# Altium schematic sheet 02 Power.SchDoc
size 386 x 246 mm
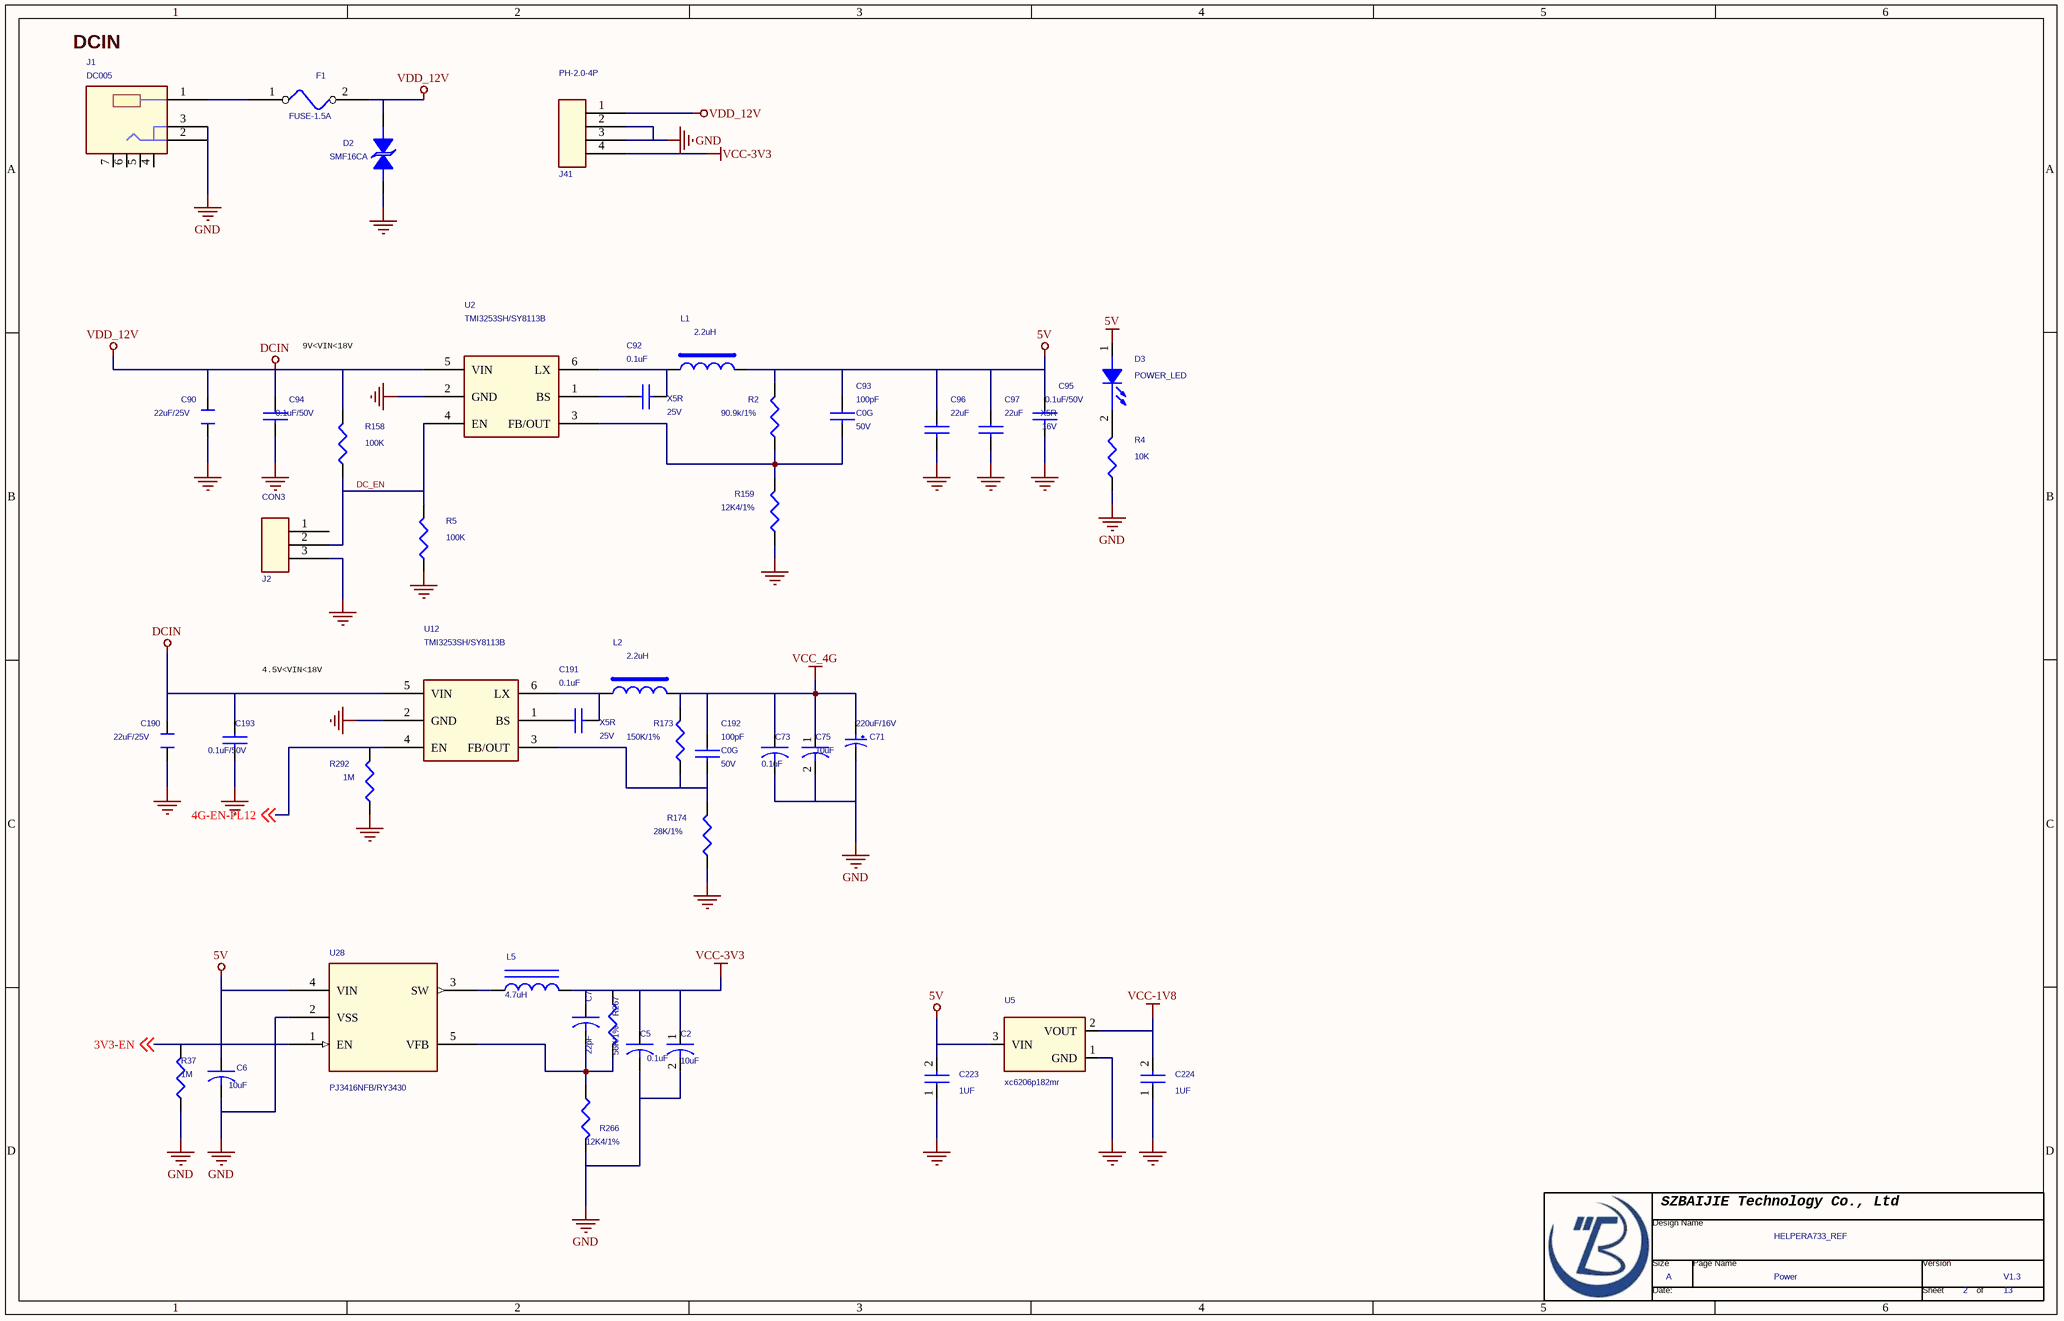
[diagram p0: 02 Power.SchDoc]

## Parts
*  Page Count: 13  Page Number: 2  Page Size: A  Title: HELPERA733_REF  RevCode: V1.3  Doc: Power  (hidden comment: TitleBlock0-BJ)  (graphical)
C2  10uF  [C0603]
C5  0.1uF  [C0402]
C6  10uF  [C0603]
C7  22pF  [C0402]
C71  220uF/16V  [RB.1/.3]
C73  0.1uF  [C0402]
C75  10uF  [C0603]
C90  22uF/25V  [C0805]
C92  0.1uF  Voltage: 25V  Dielectric: X5R  [C0402]
C93  100pF  Voltage: 50V  Dielectric: C0G  [C0402]
C94  0.1uF/50V  [C0402]
C95  0.1uF/50V  Voltage: 16V  Dielectric: X5R  [C0402]
C96  22uF  [C0805]
C97  22uF  [C0805]
C190  22uF/25V  [C0805]
C191  0.1uF  Voltage: 25V  Dielectric: X5R  [C0402]
C192  100pF  Voltage: 50V  Dielectric: C0G  [C0402]
C193  0.1uF/50V  [C0402]
C223  1UF  [C0402]
C224  1UF  [C0402]
D2  SMF16CA  [SOD123]
D3  POWER_LED  [D0603]
F1  FUSE-1.5A  [F1812]
J1  DC005  [TSH-3865D]
J2  CON3  [SS-12F44(1P2T)]
J41  PH-2.0-4P  [PH-2.0-4P]
L1  2.2uH  [4018]
L2  2.2uH  [4018]
L5  4.7uH  [4018]
R2  90.9k/1%  [R0402]
R4  10K  [R0402]
R5  100K  [R0402]
R37  1M  [R0402]
R158  100K  [R0402]
R159  12K4/1%  [R0402]
R173  150K/1%  [R0402]
R174  28K/1%  [R0402]
R266  12K4/1%  [R0402]
R267  56K/1%  [R0402]
R292  1M  [R0402]
U2  TMI3253SH/SY8113B  [SOT23-6]
U5  xc6206p182mr  [SOT5P95B160_300H130]
U12  TMI3253SH/SY8113B  [SOT23-6]
U28  PJ3416NFB/RY3430  [SOT23-5]

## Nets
5V: C6.1 C93.1 C95.1 C96.1 C97.1 C223.2 D3.1(ANODE) L1.2 R2.1 U5.3(VIN) U28.4(VIN)
DCIN: C90.1 C94.1 C190.1 C193.1 D2.2 F1.2 J41.1 R158.1 U2.5(VIN) U12.5(VIN)  [also labelled VDD_12V]
GND: C2.2 C5.2 C6.2 C71.2(M) C73.2 C75.2 C90.2 C94.2 C95.2 C96.2 C97.2 C190.2 C193.2 C223.1 C224.1 D2.1 J1.2 J1.3 J2.3 J41.2 J41.3 R4.1 R5.2 R37.1 R159.2 R174.2 R266.2 R292.2 U2.2(GND) U5.1(GND) U12.2(GND) U28.2(VSS)
VCC-1V8: C224.2 U5.2(VOUT)
VCC-3V3: C2.1 C5.1 C7.1 J41.4 L5.2 R267.1
VCC_4G: C71.1(P) C73.1 C75.1 C192.1 L2.2 R173.1
3V3-EN: R37.2 U28.1(EN) ; off-sheet 3V3-EN
4G-EN-PL12: R292.1 U12.4(EN) ; off-sheet 4G-EN-PL12
DC_EN: J2.2 R5.1 R158.2 U2.4(EN)
NetC7_2: C7.2 R266.1 R267.2 U28.5(VFB)
NetC92_1: C92.1 U2.1(BS)
NetC92_2: C92.2 L1.1 U2.6(LX)
NetC93_2: C93.2 R2.2 R159.1 U2.3(FB/OUT)
NetC191_1: C191.1 U12.1(BS)
NetC191_2: C191.2 L2.1 U12.6(LX)
NetC192_2: C192.2 R173.2 R174.1 U12.3(FB/OUT)
NetD3_2: D3.2(CATHODE) R4.2
NetF1_1: F1.1 J1.1
NetL5_1: L5.1 U28.3(SW)

Not connected (* = marked no-connect by the designer): J1 4 5 6 7; J2 1

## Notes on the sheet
- (near J1) DCIN
- 9V<VIN<18V
- 4.5V<VIN<18V

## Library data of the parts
C2 C75 = CAPACITOR_0_Dup2
C5-C7 C73 = CAPACITOR
C71 = CAP-T-33uF-C-16V: TOL: 10%; TEN: <TEN>
C90 C190 = CAPACITOR_0_Dup1
C92 C191 C193 = CAP NP_3: cap,100.00nF,+/-10%,25V,X5R,C0402; Tolerance: 10%; Priority: A
C93 C192 = CAP NP_3: cap,100.00pF,+/-5%,50V,C0G,C0402; Priority: A; Tolerance: 5%
C94 = CAP NP_3: cap,100.00nF,+/-10%,25V,X5R,C0402; Priority: A; Tolerance: 10%
C95 = CAP NP_3: cap,100.00nF,+/-10%,16V,X5R,C0402; Tolerance: 10%; Priority: A
C96 = CAP NP_3: cap,22.00uF,+/-10%,10V,X5R,C0805; Priority: A; Tolerance: 10%
C97 = CAP NP_3: cap,22.00uF,+/-10%,10V,X5R,C0805; Tolerance: 10%; Priority: A
C223 C224 = CAP NP_0
D2 = DIODE TVS BI-DIR
D3 = LED_0
F1 = FUSE_1
J1 = PHONOJACK_3: ￠3.5DC电源座　前插后贴　5PIN，两定位柱，高4.7mm; PART NUMBER: ZDC-BCT05-1000; Vendor: 质友; SPREADWIN PN: E10000040A
J41 = CON2_0
L1 L2 = ind1: Power Inductor,3.3uH,0.2,IND_404030; DC Resistor: 0.04ohm; Isat: 3.3A; Resonace frequency: 38M; Irms: 2.4A; Tolerance: 20%; Priority: A
L5 = INDUCTOR IRON
R2 R5 R158 R159 R173 R174 R292 = RESISTOR_1: RES,thick film,47KOhm,+/-5%,1/16W,SMD0402
R4 = R_Dup5
R37 = RESISTOR_Dup1
R266 R267 = R_Dup4
U2 U12 = DCDC_SY8113: Priority: A
U5 = SGM2028_0: ID: U-IC0031; Parameter: SOT23-5,input 2.5~5.5V,current=0.5A
U28 = XC9235_0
